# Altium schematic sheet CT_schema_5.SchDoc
size 284 x 245 mm
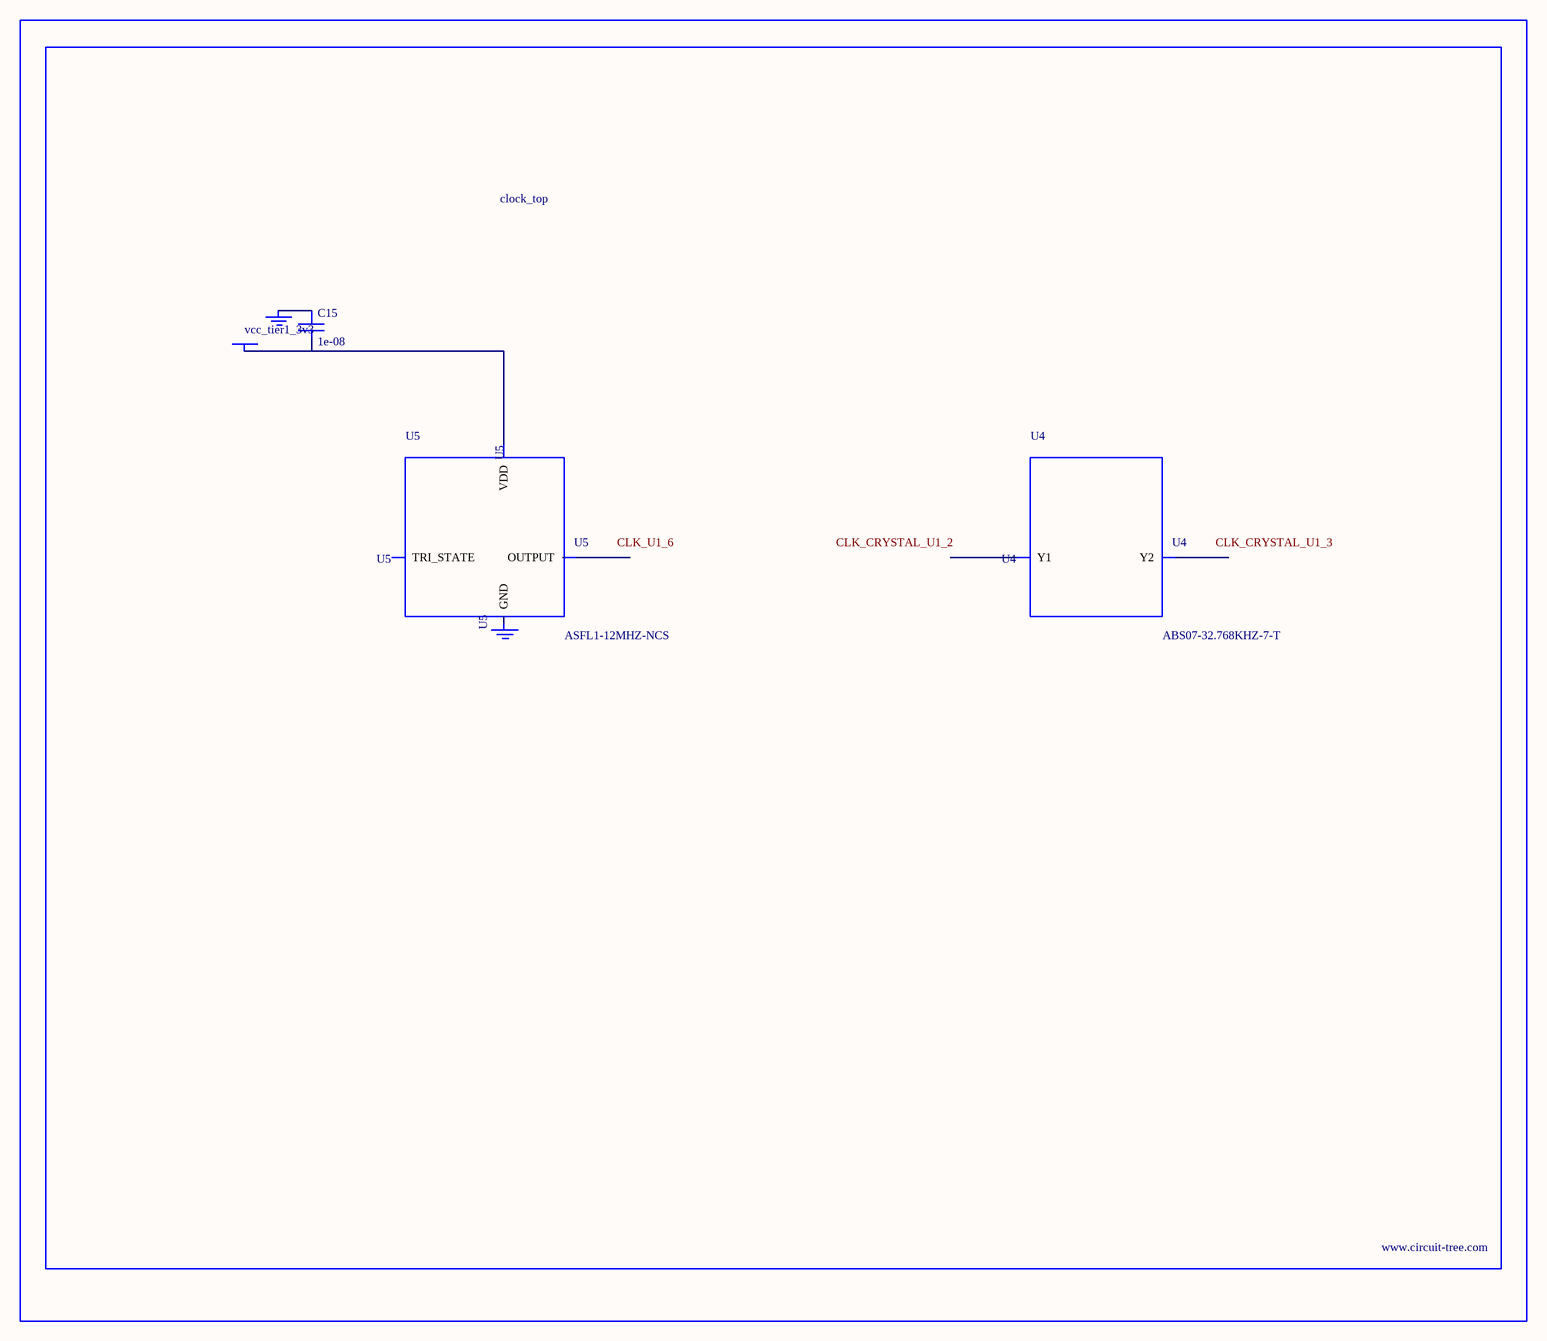
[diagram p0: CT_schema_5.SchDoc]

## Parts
BORDER4  (no value)
C15  1e-08  [C0402]
GND_INSTANCE_4_0  (no value)
GND_INSTANCE_4_1  (no value)
POWER_INSTANCE_4_0  vcc_tier1_3v3
U4  ABS07-32.768KHZ-7-T  [ABS07-32.768KHZ-7-T]
U5  ASFL1-12MHZ-NCS  [ASFL1]

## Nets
NetC15_1: C15.1 GND_INSTANCE_4_0.0(GND)
NetC15_2: C15.2 POWER_INSTANCE_4_0.0(PWR) U5.4(VDD)

Not connected (* = marked no-connect by the designer): GND_INSTANCE_4_1 0(GND); U4 1(Y1) 2(Y2); U5 1(TRI_STATE) 2(GND) 3(OUTPUT)

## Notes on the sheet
- Labels drawn without touching a wire or pin: CLK_CRYSTAL_U1_2, CLK_CRYSTAL_U1_3, CLK_U1_6

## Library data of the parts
BORDER4 = BORDER_PAGE4
C15 = C0402C103K3RAC
GND_INSTANCE_4_0 GND_INSTANCE_4_1 = GND
POWER_INSTANCE_4_0 = PWR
